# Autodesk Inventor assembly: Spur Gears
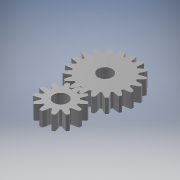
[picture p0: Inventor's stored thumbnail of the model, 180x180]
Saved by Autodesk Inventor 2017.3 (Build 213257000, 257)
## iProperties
ClientObjectVersion: 1
Created: 2020-03
Part Number: Spur Gears
Document SubType Name: Assembly
Designer: Tim_G
Categories: <?xml version="1.0" encoding="UTF-16"?> <MemberInstance><Categories><FamilyTemplate/><ParamToTemplateMap><ParamToTemplate><ParamToTemplate CategoryParameter="//
Author: Tim_G
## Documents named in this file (3)
- C:\Users\Tim_G\OneDrive - McMaster University\Documents\Documents\Books\McMaster First Year Courses\Winter Engineering 1C03\Project\Project Files (Prosthetic Frame Assembly)\Hand Assembly\Design Accelerator\Spur Gears3.iam
- C:\Users\Tim_G\OneDrive - McMaster University\Documents\Documents\Books\McMaster First Year Courses\Winter Engineering 1C03\Project\Project Files (Prosthetic Frame Assembly)\Hand Assembly\Design Accelerator\Spur Gear13.ipt
- C:\Users\Tim_G\OneDrive - McMaster University\Documents\Documents\Books\McMaster First Year Courses\Winter Engineering 1C03\Project\Project Files (Prosthetic Frame Assembly)\Hand Assembly\Design Accelerator\Spur Gear23.ipt
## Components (2 placed, 2 different names)
1. Spur Gear1:1 — Rotation:1
2. Spur Gear2:1 — Rotation:1
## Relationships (1: RelateRotation 1)
- Rotation:1 [RelateRotation]: Spur Gear1:1 ↔ Spur Gear2:1
